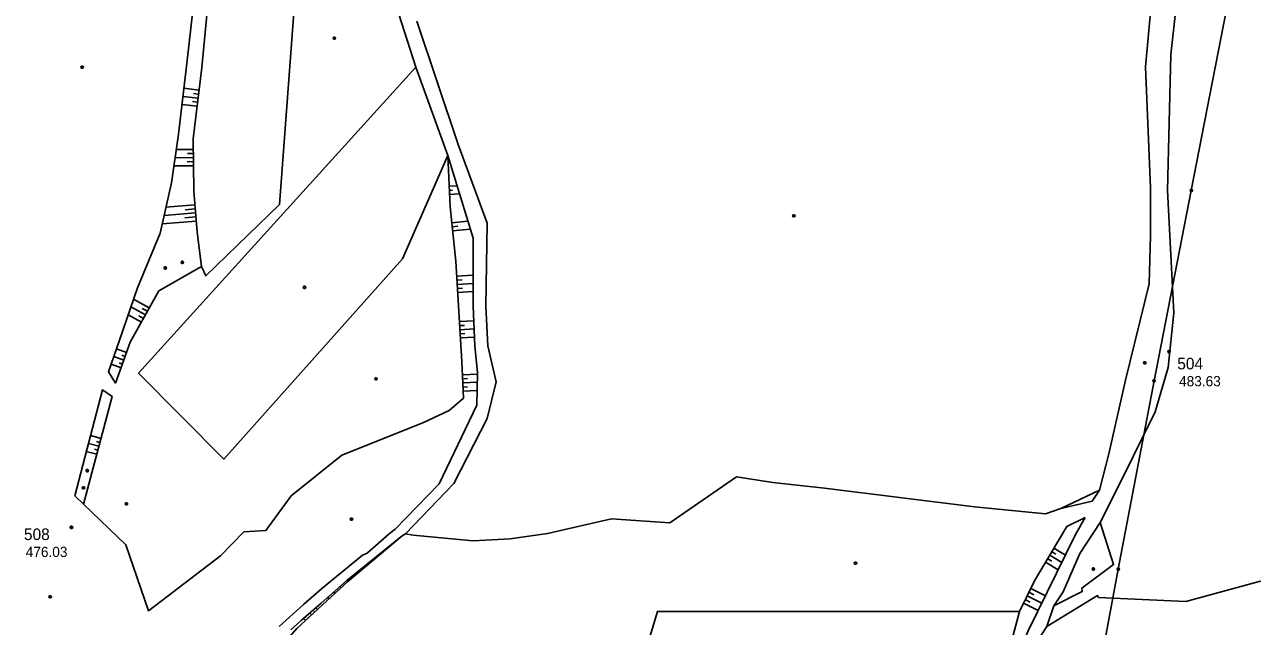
# Model space of a CAD drawing. Extents: x -664960 to -662754, y -993849 to -991145.
# Drawn here: x -664886.4 to -664525.5, y -993281.2 to -993104.4 of the extents above; entities that cross this region are included whole.
import ezdxf

# ---------------------------------------------------------------- set-up
doc = ezdxf.new("R2010")
doc.units = 0
for name, color, linetype in [('Vrstva 1', 7, 'Continuous'), ('Vrstva 13', 7, 'Continuous'), ('Vrstva 18', 7, 'Continuous'), ('Vrstva 27', 7, 'Continuous'), ('Vrstva 37', 7, 'Continuous'), ('Vrstva 57', 7, 'Continuous'), ('Vrstva 63', 7, 'Continuous'), ('Vrstva 8', 7, 'Continuous')]:
    doc.layers.add(name, color=color, linetype=linetype)

msp = doc.modelspace()

# ---------------------------------------------------------------- linework, layer by layer
at = {"layer": 'Vrstva 13'}
for points in [[(-664795.153, -993108.039), (-664794.973, -993108.339), (-664795.153, -993108.639), (-664795.513, -993108.639), (-664795.693, -993108.339), (-664795.513, -993108.039), (-664795.153, -993108.039)], [(-664869.288, -993116.599), (-664869.108, -993116.899), (-664869.288, -993117.199), (-664869.648, -993117.199), (-664869.828, -993116.899), (-664869.648, -993116.599), (-664869.288, -993116.599)], [(-664660.097, -993160.265), (-664659.917, -993160.565), (-664660.097, -993160.865), (-664660.457, -993160.865), (-664660.637, -993160.565), (-664660.457, -993160.265), (-664660.097, -993160.265)], [(-664844.861, -993175.591), (-664844.681, -993175.891), (-664844.861, -993176.191), (-664845.221, -993176.191), (-664845.401, -993175.891), (-664845.221, -993175.591), (-664844.861, -993175.591)], [(-664839.847, -993173.934), (-664839.667, -993174.234), (-664839.847, -993174.534), (-664840.207, -993174.534), (-664840.387, -993174.234), (-664840.207, -993173.934), (-664839.847, -993173.934)], [(-664803.939, -993181.276), (-664803.759, -993181.576), (-664803.939, -993181.876), (-664804.299, -993181.876), (-664804.479, -993181.576), (-664804.299, -993181.276), (-664803.939, -993181.276)], [(-664556.984, -993203.419), (-664556.804, -993203.719), (-664556.984, -993204.019), (-664557.344, -993204.019), (-664557.524, -993203.719), (-664557.344, -993203.419), (-664556.984, -993203.419)], [(-664782.929, -993208.135), (-664782.749, -993208.435), (-664782.929, -993208.735), (-664783.289, -993208.735), (-664783.469, -993208.435), (-664783.289, -993208.135), (-664782.929, -993208.135)], [(-664867.781, -993235.129), (-664867.601, -993235.429), (-664867.781, -993235.729), (-664868.141, -993235.729), (-664868.321, -993235.429), (-664868.141, -993235.129), (-664867.781, -993235.129)], [(-664868.879, -993240.188), (-664868.699, -993240.488), (-664868.879, -993240.788), (-664869.239, -993240.788), (-664869.419, -993240.488), (-664869.239, -993240.188), (-664868.879, -993240.188)], [(-664790.105, -993249.377), (-664789.925, -993249.677), (-664790.105, -993249.977), (-664790.465, -993249.977), (-664790.645, -993249.677), (-664790.465, -993249.377), (-664790.105, -993249.377)], [(-664641.987, -993262.284), (-664641.807, -993262.584), (-664641.987, -993262.884), (-664642.347, -993262.884), (-664642.527, -993262.584), (-664642.347, -993262.284), (-664641.987, -993262.284)], [(-664572.072, -993264.023), (-664571.892, -993264.323), (-664572.072, -993264.623), (-664572.432, -993264.623), (-664572.612, -993264.323), (-664572.432, -993264.023), (-664572.072, -993264.023)]]:
    msp.add_lwpolyline(points, dxfattribs=at)
at = {"layer": 'Vrstva 18'}
for points in [[(-664872.45, -993251.76), (-664872.27, -993252.06), (-664872.45, -993252.36), (-664872.81, -993252.36), (-664872.99, -993252.06), (-664872.81, -993251.76), (-664872.45, -993251.76)], [(-664878.68, -993272.19), (-664878.5, -993272.49), (-664878.68, -993272.79), (-664879.04, -993272.79), (-664879.22, -993272.49), (-664879.04, -993272.19), (-664878.68, -993272.19)]]:
    msp.add_lwpolyline(points, dxfattribs=at)
at = {"layer": 'Vrstva 27'}
for points in [[(-664776.38, -993101.37), (-664771.43, -993116.89), (-664761.99, -993142.87), (-664754.57, -993167.1), (-664754.55, -993187.06), (-664754.04, -993198.75), (-664753.31, -993206.65), (-664753.45, -993216.22), (-664764.52, -993239.29), (-664777.45, -993252.62), (-664779.14, -993253.87), (-664785.73, -993259.69), (-664787.02, -993260.25), (-664799.13, -993270.1), (-664804.41, -993274.79), (-664811.54, -993281.21)], [(-664808.09, -993282.21), (-664805.1, -993279.44), (-664799.2, -993274.37), (-664791.69, -993267.72), (-664775.38, -993254.53), (-664774.42, -993254.01), (-664760.25, -993239.24), (-664750.41, -993220.09), (-664747.78, -993209.33), (-664750.22, -993198.74), (-664750.78, -993187.1), (-664750.42, -993162.68), (-664758.94, -993139.61), (-664771.07, -993103.34)], [(-664570.5, -993241.14), (-664572.587, -993244.411), (-664581.807, -993246.578)], [(-664574.672, -993249.156), (-664577.47, -993254.18), (-664591.39, -993282.44), (-664599.28, -993301.59), (-664602.71, -993317.41)], [(-664587.62, -993283.78), (-664585.93, -993281.177), (-664583.879, -993275.133), (-664581.1, -993271.07), (-664576.21, -993259.73), (-664570.3, -993250.68)]]:
    msp.add_lwpolyline(points, dxfattribs=at)
at = {"layer": 'Vrstva 37'}
for points in [[(-664543.3, -993152.784), (-664543.12, -993153.084), (-664543.3, -993153.384), (-664543.66, -993153.384), (-664543.84, -993153.084), (-664543.66, -993152.784), (-664543.3, -993152.784)], [(-664554.253, -993208.757), (-664554.073, -993209.057), (-664554.253, -993209.357), (-664554.613, -993209.357), (-664554.793, -993209.057), (-664554.613, -993208.757), (-664554.253, -993208.757)], [(-664564.765, -993264.053), (-664564.585, -993264.353), (-664564.765, -993264.653), (-664565.125, -993264.653), (-664565.305, -993264.353), (-664565.125, -993264.053), (-664564.765, -993264.053)]]:
    msp.add_lwpolyline(points, dxfattribs=at)
at = {"layer": 'Vrstva 57'}
msp.add_lwpolyline([(-664522.999, -993424.664), (-664549.676, -993372.01), (-664575.68, -993321.894), (-664564.945, -993264.353), (-664554.433, -993209.057), (-664543.48, -993153.084), (-664531.665, -993092.329), (-664519.333, -993029.427), (-664507.314, -992967.479), (-664498.291, -992920.92), (-664487.02, -992863.072)], dxfattribs=at)
at = {"layer": 'Vrstva 63'}
for p, q in [((-664835.083, -993123.617), (-664839.543, -993123.084)), ((-664835.368, -993126), (-664839.826, -993125.467)), ((-664835.225, -993124.809), (-664836.71, -993124.631)), ((-664835.653, -993128.383), (-664840.109, -993127.85)), ((-664835.511, -993127.192), (-664836.995, -993127.014)), ((-664836.774, -993141.053), (-664841.804, -993141.095)), ((-664836.754, -993143.453), (-664842.153, -993143.498)), ((-664836.744, -993144.653), (-664838.603, -993144.668)), ((-664836.764, -993142.253), (-664838.5, -993142.267)), ((-664836.733, -993145.853), (-664842.502, -993145.901)), ((-664761.576, -993151.878), (-664759.264, -993151.772)), ((-664761.521, -993153.077), (-664760.649, -993153.037)), ((-664761.466, -993154.276), (-664758.538, -993154.141)), ((-664836.331, -993157.321), (-664844.841, -993158.05)), ((-664836.228, -993158.516), (-664839.188, -993158.77)), ((-664835.921, -993162.103), (-664845.945, -993162.962)), ((-664836.126, -993159.712), (-664845.393, -993160.506)), ((-664836.023, -993160.907), (-664839.235, -993161.183)), ((-664760.817, -993162.607), (-664756.094, -993162.122)), ((-664760.694, -993163.801), (-664759.043, -993163.631)), ((-664760.572, -993164.994), (-664755.378, -993164.461)), ((-664759.394, -993178.308), (-664754.559, -993178.018)), ((-664759.322, -993179.506), (-664757.736, -993179.411)), ((-664759.251, -993180.704), (-664754.557, -993180.422)), ((-664759.179, -993181.902), (-664757.639, -993181.809)), ((-664759.107, -993183.1), (-664754.554, -993182.826)), ((-664850.88, -993189.671), (-664855.131, -993187.313)), ((-664849.716, -993187.572), (-664854.337, -993185.009)), ((-664850.298, -993188.621), (-664851.775, -993187.802)), ((-664852.044, -993191.769), (-664855.925, -993189.617)), ((-664851.462, -993190.72), (-664852.816, -993189.969)), ((-664758.595, -993191.633), (-664754.362, -993191.379)), ((-664758.523, -993192.831), (-664757.12, -993192.747)), ((-664758.451, -993194.029), (-664754.257, -993193.777)), ((-664758.379, -993195.226), (-664756.989, -993195.143)), ((-664758.307, -993196.424), (-664754.152, -993196.175)), ((-664857.213, -993202.979), (-664860.164, -993201.922)), ((-664856.403, -993200.72), (-664859.382, -993199.652)), ((-664856.808, -993201.849), (-664857.795, -993201.496)), ((-664858.022, -993205.238), (-664860.946, -993204.191)), ((-664857.617, -993204.109), (-664858.595, -993203.758)), ((-664757.717, -993207.265), (-664753.316, -993207.069)), ((-664757.663, -993208.464), (-664756.221, -993208.4)), ((-664757.61, -993209.663), (-664753.351, -993209.473)), ((-664757.556, -993210.862), (-664756.162, -993210.799)), ((-664757.503, -993212.06), (-664753.386, -993211.877)), ((-664864.532, -993228.279), (-664867.625, -993227.449)), ((-664863.909, -993225.961), (-664867.019, -993225.126)), ((-664864.221, -993227.12), (-664865.253, -993226.843)), ((-664865.154, -993230.597), (-664868.232, -993229.771)), ((-664864.843, -993229.438), (-664865.87, -993229.162)), ((-664774.42, -993254.01), (-664772.21, -993254.41)), ((-664585.062, -993260.264), (-664581.504, -993262.369)), ((-664584.451, -993259.231), (-664583.292, -993259.917)), ((-664583.84, -993258.198), (-664580.44, -993260.21)), ((-664786.159, -993263.621), (-664786.221, -993263.547)), ((-664785.241, -993262.848), (-664785.413, -993262.644)), ((-664784.324, -993262.074), (-664784.376, -993262.012)), ((-664783.407, -993261.3), (-664783.547, -993261.134)), ((-664586.284, -993262.329), (-664582.567, -993264.528)), ((-664585.673, -993261.297), (-664584.462, -993262.013)), ((-664787.076, -993264.395), (-664787.28, -993264.153)), ((-664795.148, -993271.484), (-664795.503, -993271.097)), ((-664794.264, -993270.673), (-664794.377, -993270.549)), ((-664793.379, -993269.862), (-664793.706, -993269.505)), ((-664591.2, -993271.164), (-664589.766, -993271.879)), ((-664590.665, -993270.09), (-664586.364, -993272.236)), ((-664796.916, -993273.107), (-664797.301, -993272.688)), ((-664796.032, -993272.295), (-664796.155, -993272.161)), ((-664592.808, -993274.385), (-664588.485, -993276.542)), ((-664592.272, -993273.311), (-664590.834, -993274.029)), ((-664591.736, -993272.238), (-664587.424, -993274.389)), ((-664802.942, -993278.634), (-664803.121, -993278.439)), ((-664802.058, -993277.823), (-664802.57, -993277.265)), ((-664801.174, -993277.012), (-664801.335, -993276.836)), ((-664800.289, -993276.201), (-664800.748, -993275.7)), ((-664803.826, -993279.446), (-664804.391, -993278.831))]:
    msp.add_line(p, q, dxfattribs=at)
for points in [[(-664831.55, -993037.76), (-664833.11, -993020.67), (-664827.81, -993017.45), (-664827.48, -993033.32), (-664827.77, -993050.54), (-664829.5, -993067.38), (-664831.04, -993082.99), (-664834.29, -993116.99), (-664836.8, -993137.97), (-664836.67, -993153.36), (-664835.64, -993165.38), (-664834.4, -993175.41), (-664846.97, -993182.62), (-664855.3, -993197.64), (-664859.62, -993209.7), (-664861.71, -993206.41), (-664858.51, -993197.12), (-664853.19, -993181.68), (-664846.56, -993165.7), (-664843.22, -993150.84), (-664841.14, -993136.53), (-664838.57, -993114.89), (-664835.19, -993084.54), (-664831.55, -993037.76)], [(-664827.81, -993017.45), (-664802.73, -993020.1), (-664805.16, -993069.86), (-664805.5, -993077.19), (-664811.42, -993157.27), (-664833.14, -993178.18), (-664834.4, -993175.41)], [(-664541.29, -993068.2), (-664546.848, -993089.32), (-664549.459, -993113.136), (-664550.45, -993153.095), (-664548.592, -993189.058), (-664550.275, -993205.084), (-664554.048, -993218.194), (-664563.831, -993237.797), (-664570.304, -993250.681), (-664566.308, -993263.028), (-664575.608, -993269.908), (-664575.58, -993270.94), (-664583.879, -993275.133)], [(-664554.25, -993087.94), (-664556.941, -993116.782), (-664555.472, -993152.376), (-664555.433, -993166.316), (-664555.866, -993180.523), (-664562.815, -993208.847), (-664567.677, -993230.44), (-664570.498, -993241.142), (-664581.807, -993246.578), (-664586.352, -993248.126), (-664607.195, -993246.026), (-664651.264, -993240.564), (-664666.443, -993238.925), (-664677.101, -993237.259), (-664696.743, -993250.798), (-664713.926, -993249.625), (-664732.687, -993253.923), (-664743.665, -993255.481), (-664754.532, -993256.093), (-664772.207, -993254.41)], [(-664761.99, -993142.87), (-664775.32, -993173.18), (-664827.86, -993232.05), (-664852.89, -993206.8), (-664771.43, -993116.89)], [(-664761.99, -993142.87), (-664761.3, -993157.9), (-664759.66, -993173.88), (-664757.89, -993203.38), (-664757.41, -993214.14), (-664761.59, -993217.72), (-664769.32, -993221.34), (-664793.16, -993230.86), (-664808.04, -993242.87), (-664815.46, -993252.99), (-664821.93, -993253.45), (-664828.83, -993260.44), (-664849.95, -993276.58), (-664856.65, -993257.22), (-664869.09, -993245.26), (-664871.65, -993242.86)], [(-664390.32, -993186.44), (-664389.79, -993175.91), (-664392.34, -993175.45), (-664396.16, -993182.93), (-664400.26, -993208.18), (-664413.92, -993213.67), (-664433.36, -993231.7), (-664461.53, -993243.28), (-664483.35, -993253.09), (-664486.43, -993263.9), (-664505.17, -993263.96), (-664523.48, -993268.03), (-664545.04, -993273.84), (-664570.73, -993272.74), (-664571.013, -993272.12), (-664585.93, -993281.177)], [(-664869.09, -993245.26), (-664860.61, -993213.67), (-664863.51, -993211.69), (-664871.65, -993242.86)], [(-664856.27, -993244.85), (-664856.09, -993245.15), (-664856.27, -993245.45), (-664856.63, -993245.45), (-664856.81, -993245.15), (-664856.63, -993244.85), (-664856.27, -993244.85)], [(-664630.397, -993424.579), (-664632.486, -993421.317), (-664630.616, -993416.587), (-664624.676, -993401.09), (-664616.499, -993384.579), (-664612.175, -993368.846), (-664609.436, -993355.208), (-664606.449, -993334.731), (-664604.668, -993316.902), (-664593.999, -993276.773), (-664589.529, -993267.814), (-664580.068, -993251.823), (-664574.672, -993249.156)], [(-664840.72, -993373.73), (-664838.01, -993373.23), (-664835.42, -993341.94), (-664835.17, -993324.78), (-664831.99, -993313.34), (-664818.8, -993296.03), (-664806.36, -993281.77), (-664791.35, -993268), (-664775.38, -993254.53)], [(-664616.5, -993384.58), (-664678.71, -993381.7), (-664732.06, -993381.95), (-664700.4, -993276.77), (-664594, -993276.77)]]:
    msp.add_lwpolyline(points, dxfattribs=at)
at = {"layer": 'Vrstva 8'}
for points in [[(-664549.82, -993200.17), (-664549.64, -993200.47), (-664549.82, -993200.77), (-664550.18, -993200.77), (-664550.36, -993200.47), (-664550.18, -993200.17), (-664549.82, -993200.17)], [(-664872.42, -993251.81), (-664872.24, -993252.11), (-664872.42, -993252.41), (-664872.78, -993252.41), (-664872.96, -993252.11), (-664872.78, -993251.81), (-664872.42, -993251.81)]]:
    msp.add_lwpolyline(points, dxfattribs=at)

# ---------------------------------------------------------------- texts
at = {"layer": 'Vrstva 1'}
for s, p in [('504', (-664547.6, -993205.67)), ('508', (-664886.569, -993255.817))]:
    msp.add_text(s, height=3.4, dxfattribs=at).set_placement(p)
at = {"layer": 'Vrstva 63'}
for s, p in [('483.63', (-664547.076, -993210.65)), ('476.03', (-664886.045, -993260.797))]:
    msp.add_text(s, height=3, dxfattribs=at).set_placement(p)

doc.saveas('drawing.dxf')
